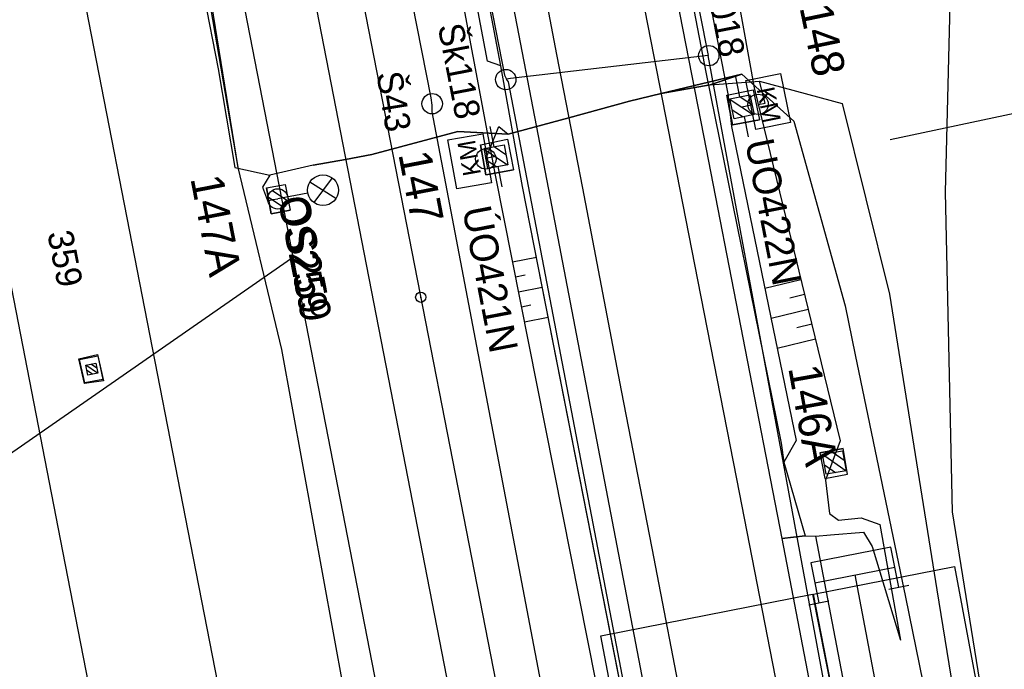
# Model space of a CAD drawing. Extents: x -545967 to -545044, y -1122650 to -1118491.
# Drawn here: x -545744.88 to -545696.59, y -1119225.35 to -1119193.49 of the extents above; entities that cross this region are included whole.
import ezdxf

# ---------------------------------------------------------------- set-up
doc = ezdxf.new("R2010")
doc.units = 0
for name, color, linetype in [('osvětlené plochy-hodnota-obrys', 7, 'Continuous'), ('Vrstva 1', 7, 'Continuous'), ('Vrstva 1 - Koleje', 7, 'Continuous'), ('Vrstva 11', 7, 'Continuous'), ('Vrstva 11 - Trakce', 7, 'Continuous'), ('Vrstva 12', 7, 'Continuous'), ('Vrstva 12 - Trakce zaklady', 7, 'Continuous'), ('Vrstva 15_zarazedla', 7, 'Continuous'), ('Vrstva 19 - Staniceni', 7, 'Continuous'), ('Vrstva 25', 7, 'Continuous'), ('Vrstva 25 - silnoproud prvky', 7, 'Continuous'), ('Vrstva 26', 7, 'Continuous'), ('Vrstva 26 - silnoproud', 7, 'Continuous'), ('Vrstva 28 - zabzar', 7, 'Continuous'), ('Vrstva 31', 7, 'Continuous'), ('Vrstva 32', 7, 'Continuous'), ('Vrstva 4 - Teren - stezky - prechody - plochy', 7, 'Continuous'), ('Vrstva 43', 7, 'Continuous'), ('Vrstva 44', 7, 'Continuous'), ('Vrstva 48', 7, 'Continuous'), ('Vrstva 49', 7, 'Continuous'), ('Vrstva 50', 7, 'Continuous'), ('Vrstva 51', 7, 'Continuous'), ('Vrstva 63', 7, 'Continuous')]:
    doc.layers.add(name, color=color, linetype=linetype)

msp = doc.modelspace()

# ---------------------------------------------------------------- linework, layer by layer
at = {"layer": 'osvětlené plochy-hodnota-obrys'}
for points in [[(-545700.341, -1119250.428), (-545705.955, -1119221.665), (-545699.039, -1119220.315), (-545660.607, -1119425.918), (-545653.752, -1119372.856), (-545653.095, -1119348.321), (-545657.119, -1119319.988), (-545685.945, -1119192.198), (-545694.33, -1119168.5)], [(-545664.282, -1119515.639), (-545680.447, -1119467.233), (-545736.202, -1119180.74), (-545730.573, -1119179.645)], [(-545730.573, -1119179.645), (-545675.345, -1119462.605), (-545660.82, -1119505.941)], [(-545716.386, -1119223.717), (-545705.994, -1119221.66), (-545669.439, -1119408.759), (-545659.4, -1119462.635), (-545647.69, -1119521.347), (-545640.519, -1119558.729), (-545633.585, -1119589.698), (-545629.517, -1119613.814), (-545623.042, -1119645.057), (-545619.034, -1119667.556), (-545607.519, -1119727.517)], [(-545610.895, -1119760.665), (-545622.836, -1119699.488), (-545637.26, -1119626.872), (-545653.542, -1119543.449), (-545716.386, -1119223.717)]]:
    msp.add_lwpolyline(points, dxfattribs=at)
at = {"layer": 'Vrstva 1'}
for points in [[(-545771.025, -1119042.195), (-545765.518, -1119070.46), (-545759.655, -1119100.537), (-545754.322, -1119127.883), (-545749.142, -1119154.443), (-545741.38, -1119194.232), (-545736.638, -1119218.552), (-545732.259, -1119241.007)], [(-545771.689, -1119071.297), (-545765.82, -1119101.405), (-545760.255, -1119129.935), (-545755.249, -1119155.634), (-545747.474, -1119195.477), (-545742.774, -1119219.556), (-545738.366, -1119242.197)], [(-545732.996, -1119179.254), (-545727.764, -1119206.17), (-545723.954, -1119225.738), (-545721.389, -1119238.891)]]:
    msp.add_lwpolyline(points, dxfattribs=at)
at = {"layer": 'Vrstva 1 - Koleje'}
for points in [[(-545733.999, -1119091.546), (-545732.95, -1119096.936), (-545731.205, -1119105.879), (-545729.373, -1119115.292), (-545728.267, -1119120.965), (-545726.468, -1119130.178), (-545724.605, -1119139.732), (-545722.574, -1119150.154), (-545720.702, -1119159.751), (-545718.638, -1119170.336), (-545716.601, -1119180.775), (-545714.642, -1119190.838), (-545712.795, -1119200.311), (-545711.639, -1119206.25), (-545709.729, -1119216.005), (-545707.216, -1119228.928), (-545705.339, -1119238.544), (-545703.888, -1119245.98)], [(-545738.202, -1119092.228), (-545736.387, -1119101.709), (-545734.567, -1119111.273), (-545732.861, -1119120.206), (-545731.063, -1119129.63), (-545729.36, -1119138.55), (-545727.68, -1119147.349), (-545726.123, -1119155.516), (-545724.233, -1119165.426), (-545722.398, -1119175.037), (-545720.387, -1119185.566), (-545718.546, -1119195.193), (-545717.286, -1119201.759), (-545715.378, -1119211.671), (-545713.882, -1119219.417), (-545712.258, -1119227.812), (-545710.337, -1119237.731), (-545708.555, -1119246.894)], [(-545703.92, -1119220.722), (-545702.554, -1119227.966), (-545700.678, -1119237.615), (-545699.221, -1119245.067)]]:
    msp.add_lwpolyline(points, dxfattribs=at)
at = {"layer": 'Vrstva 11'}
for p, q in [((-545741.057, -1119210.831), (-545741.642, -1119210.439)), ((-545741.106, -1119210.572), (-545741.384, -1119210.386)), ((-545741.317, -1119210.882), (-545741.591, -1119210.699))]:
    msp.add_line(p, q, dxfattribs=at)
for points in [[(-545693.484, -1119243.944), (-545696.51, -1119233.839), (-545699.129, -1119217.635), (-545699.471, -1119201.94)], [(-545741.546, -1119210.928), (-545741.643, -1119210.437), (-545741.152, -1119210.34), (-545741.055, -1119210.831), (-545741.546, -1119210.928)]]:
    msp.add_lwpolyline(points, dxfattribs=at)
msp.add_lwpolyline([(-545741.546, -1119210.928), (-545741.643, -1119210.437), (-545741.152, -1119210.34), (-545741.055, -1119210.831)], close=True, dxfattribs=at)
at = {"layer": 'Vrstva 11 - Trakce'}
for p, q in [((-545709.556, -1119197.274), (-545709.76, -1119196.291)), ((-545710.041, -1119197.395), (-545708.886, -1119198.151)), ((-545709.55, -1119197.268), (-545708.966, -1119197.651)), ((-545709.932, -1119197.914), (-545709.405, -1119198.259)), ((-545709.355, -1119198.239), (-545709.148, -1119199.227)), ((-545721.618, -1119199.719), (-545721.807, -1119198.733)), ((-545722.104, -1119199.833), (-545720.961, -1119200.607)), ((-545721.612, -1119199.714), (-545721.033, -1119200.106)), ((-545722.004, -1119200.354), (-545721.482, -1119200.707)), ((-545721.431, -1119200.687), (-545721.239, -1119201.679)), ((-545732.703, -1119202.17), (-545731.935, -1119202.687)), ((-545732.488, -1119201.863), (-545731.73, -1119202.373)), ((-545705.508, -1119214.803), (-545704.352, -1119215.609)), ((-545704.986, -1119214.71), (-545704.445, -1119215.088)), ((-545705.418, -1119215.322), (-545704.87, -1119215.705))]:
    msp.add_line(p, q, dxfattribs=at)
for points in [[(-545709.067, -1119197.167), (-545708.862, -1119198.146), (-545709.841, -1119198.351), (-545710.046, -1119197.372)], [(-545721.127, -1119199.621), (-545720.938, -1119200.602), (-545721.919, -1119200.791), (-545722.108, -1119199.81)], [(-545704.527, -1119214.628), (-545704.351, -1119215.612), (-545705.335, -1119215.788), (-545705.511, -1119214.804)]]:
    msp.add_lwpolyline(points, close=True, dxfattribs=at)
msp.add_circle((-545732.219, -1119202.28), 0.5, dxfattribs=at)
at = {"layer": 'Vrstva 12'}
msp.add_line((-545741.061, -1119209.905), (-545740.764, -1119211.198), dxfattribs=at)
for points in [[(-545741.974, -1119210.12), (-545741.061, -1119209.905), (-545741.043, -1119209.979)], [(-545741.703, -1119211.337), (-545741.974, -1119210.12), (-545741.945, -1119210.159)], [(-545740.806, -1119211.129), (-545740.764, -1119211.198), (-545741.703, -1119211.337), (-545741.686, -1119211.306)]]:
    msp.add_lwpolyline(points, dxfattribs=at)
msp.add_lwpolyline([(-545740.806, -1119211.129), (-545741.686, -1119211.306), (-545741.945, -1119210.159), (-545741.043, -1119209.979)], close=True, dxfattribs=at)
at = {"layer": 'Vrstva 12 - Trakce zaklady'}
for p, q in [((-545710.205, -1119197.185), (-545708.905, -1119196.923)), ((-545709.93, -1119198.644), (-545708.598, -1119198.395)), ((-545722.288, -1119199.621), (-545720.949, -1119199.355)), ((-545722.017, -1119201.095), (-545720.662, -1119200.846)), ((-545732.782, -1119201.73), (-545731.858, -1119201.572)), ((-545732.54, -1119203.006), (-545731.612, -1119202.833)), ((-545705.633, -1119214.741), (-545704.502, -1119214.523)), ((-545705.386, -1119216.001), (-545704.278, -1119215.779))]:
    msp.add_line(p, q, dxfattribs=at)
for points in [[(-545709.93, -1119198.644), (-545710.205, -1119197.185), (-545708.905, -1119196.923), (-545708.598, -1119198.395), (-545709.93, -1119198.644)], [(-545710.205, -1119197.185), (-545710.205, -1119197.185), (-545709.93, -1119198.644), (-545709.93, -1119198.644)], [(-545722.017, -1119201.095), (-545722.288, -1119199.621), (-545720.949, -1119199.355), (-545720.662, -1119200.846), (-545722.017, -1119201.095)], [(-545720.949, -1119199.355), (-545720.949, -1119199.355), (-545720.662, -1119200.846), (-545720.662, -1119200.846)], [(-545722.288, -1119199.621), (-545722.288, -1119199.621), (-545722.017, -1119201.095), (-545722.017, -1119201.095)], [(-545731.858, -1119201.572), (-545731.612, -1119202.833), (-545732.54, -1119203.006), (-545732.782, -1119201.73), (-545731.858, -1119201.572)], [(-545732.782, -1119201.73), (-545732.782, -1119201.73), (-545732.54, -1119203.006), (-545732.54, -1119203.006)], [(-545731.858, -1119201.572), (-545731.858, -1119201.572), (-545731.612, -1119202.833), (-545731.612, -1119202.833)], [(-545705.633, -1119214.741), (-545705.386, -1119216.001), (-545704.278, -1119215.779), (-545704.502, -1119214.523), (-545705.633, -1119214.741)], [(-545705.633, -1119214.741), (-545705.633, -1119214.741), (-545705.386, -1119216.001), (-545705.386, -1119216.001)]]:
    msp.add_lwpolyline(points, dxfattribs=at)
at = {"layer": 'Vrstva 15_zarazedla'}
for p, q in [((-545705.882, -1119221.108), (-545701.958, -1119220.336)), ((-545702.255, -1119221.414), (-545701.274, -1119221.221)), ((-545706.18, -1119222.185), (-545705.199, -1119221.992))]:
    msp.add_line(p, q, dxfattribs=at)
msp.add_lwpolyline([(-545701.765, -1119221.318), (-545702.15, -1119219.355), (-545706.075, -1119220.126), (-545705.69, -1119222.089)], dxfattribs=at)
at = {"layer": 'Vrstva 19 - Staniceni'}
for p, q in [((-545709.454, -1119197.759), (-545709.027, -1119197.672)), ((-545721.523, -1119200.206), (-545721.952, -1119200.283))]:
    msp.add_line(p, q, dxfattribs=at)
for points in [[(-545709.269, -1119196.477), (-545707.566, -1119196.132), (-545707.08, -1119198.525), (-545708.784, -1119198.87)], [(-545721.737, -1119201.483), (-545723.447, -1119201.791), (-545723.879, -1119199.387), (-545722.168, -1119199.08)]]:
    msp.add_lwpolyline(points, close=True, dxfattribs=at)
at = {"layer": 'Vrstva 25'}
for p, q in [((-545729.548, -1119201.252), (-545730.46, -1119202.451)), ((-545729.369, -1119202.251), (-545730.652, -1119201.46)), ((-545730.747, -1119201.992), (-545732.219, -1119202.28))]:
    msp.add_line(p, q, dxfattribs=at)
msp.add_circle((-545730.006, -1119201.85), 0.754, dxfattribs=at)
at = {"layer": 'Vrstva 25 - silnoproud prvky'}
for p, q in [((-545708.68, -1119197.591), (-545708.66, -1119197.689)), ((-545722.029, -1119200.271), (-545722.011, -1119200.369)), ((-545729.548, -1119201.252), (-545730.46, -1119202.451)), ((-545729.369, -1119202.251), (-545730.652, -1119201.46)), ((-545730.747, -1119201.992), (-545732.219, -1119202.28))]:
    msp.add_line(p, q, dxfattribs=at)
for centre, radius in [((-545708.67, -1119197.64), 0.5), ((-545722.02, -1119200.32), 0.5), ((-545730.006, -1119201.85), 0.754)]:
    msp.add_circle(centre, radius, dxfattribs=at)
at = {"layer": 'Vrstva 26'}
for points in [[(-545709.47, -1119196.16), (-545713.419, -1119197.11), (-545714.968, -1119197.483), (-545717.951, -1119198.296), (-545720.917, -1119199.104), (-545723.4, -1119198.98), (-545727.61, -1119200.1), (-545728.9, -1119200.338), (-545730.48, -1119200.63)], [(-545723.4, -1119198.98), (-545720.917, -1119199.104), (-545717.951, -1119198.296), (-545714.968, -1119197.483), (-545713.419, -1119197.11), (-545709.47, -1119196.16), (-545706.908, -1119198.458), (-545704.395, -1119207.525), (-545703.903, -1119209.931), (-545701.434, -1119221.82), (-545699.39, -1119231.84), (-545698.841, -1119235.301), (-545696.65, -1119244.564)], [(-545723.4, -1119198.98), (-545727.61, -1119200.1), (-545728.9, -1119200.338), (-545730.48, -1119200.63), (-545732.62, -1119201.11), (-545732.98, -1119201.71), (-545732.72, -1119202.36), (-545732.718, -1119202.365), (-545732.46, -1119202.3), (-545732.219, -1119202.28)]]:
    msp.add_lwpolyline(points, dxfattribs=at)
at = {"layer": 'Vrstva 26 - silnoproud'}
for points in [[(-545748.72, -1119088.787), (-545745.498, -1119105.777), (-545744.592, -1119110.019), (-545739.382, -1119138.558), (-545737.893, -1119145.12), (-545736.243, -1119151.98), (-545735.253, -1119157.79), (-545734.753, -1119161.66), (-545734.703, -1119163.85), (-545735.243, -1119167.68), (-545737.053, -1119172.51), (-545737.303, -1119173.49), (-545737.953, -1119181.49), (-545735.153, -1119195.905), (-545734.323, -1119200.74), (-545732.62, -1119201.11)], [(-545730.48, -1119200.63), (-545728.9, -1119200.338), (-545727.61, -1119200.1), (-545723.4, -1119198.98), (-545720.917, -1119199.104), (-545717.951, -1119198.296), (-545714.968, -1119197.483), (-545713.419, -1119197.11), (-545711.01, -1119196.68), (-545709.47, -1119196.16)], [(-545709.47, -1119196.16), (-545711.01, -1119196.68), (-545713.419, -1119197.11), (-545714.968, -1119197.483), (-545717.951, -1119198.296), (-545720.917, -1119199.104), (-545723.4, -1119198.98), (-545727.61, -1119200.1), (-545728.9, -1119200.338), (-545730.48, -1119200.63)], [(-545723.4, -1119198.98), (-545720.917, -1119199.104), (-545717.951, -1119198.296), (-545714.968, -1119197.483), (-545713.419, -1119197.11), (-545711.01, -1119196.68), (-545709.47, -1119196.16), (-545706.908, -1119198.458), (-545704.395, -1119207.525), (-545703.903, -1119209.931), (-545701.434, -1119221.82), (-545699.39, -1119231.84), (-545698.841, -1119235.301), (-545696.65, -1119244.564)], [(-545723.4, -1119198.98), (-545720.917, -1119199.104), (-545717.951, -1119198.296), (-545714.968, -1119197.483), (-545713.419, -1119197.11), (-545711.01, -1119196.68), (-545709.47, -1119196.16), (-545706.908, -1119198.458), (-545704.395, -1119207.525), (-545703.903, -1119209.931), (-545701.434, -1119221.82), (-545699.39, -1119231.84), (-545698.841, -1119235.301), (-545696.65, -1119244.564)], [(-545720.917, -1119199.104), (-545717.951, -1119198.296), (-545714.968, -1119197.483), (-545713.419, -1119197.11), (-545711.01, -1119196.68), (-545709.47, -1119196.16)], [(-545722.02, -1119200.32), (-545721.39, -1119198.73), (-545720.917, -1119199.104), (-545717.951, -1119198.296), (-545714.968, -1119197.483), (-545713.419, -1119197.11), (-545711.01, -1119196.68), (-545708.6, -1119196.51)], [(-545708.67, -1119197.64), (-545708.32, -1119197.58), (-545708.6, -1119196.51), (-545704.54, -1119197.6), (-545702.23, -1119206.95), (-545699.9, -1119221.45), (-545698.219, -1119231.843), (-545695.098, -1119244.26)], [(-545723.4, -1119198.98), (-545727.61, -1119200.1), (-545728.9, -1119200.338), (-545730.48, -1119200.63), (-545732.62, -1119201.11), (-545732.98, -1119201.71), (-545732.72, -1119202.36), (-545732.718, -1119202.365), (-545732.46, -1119202.3), (-545732.219, -1119202.28)], [(-545723.4, -1119198.98), (-545727.61, -1119200.1), (-545728.9, -1119200.338), (-545730.48, -1119200.63), (-545732.62, -1119201.11)]]:
    msp.add_lwpolyline(points, dxfattribs=at)
at = {"layer": 'Vrstva 28 - zabzar'}
msp.add_lwpolyline([(-545724.371, -1119249.989), (-545724.69, -1119248.61), (-545727.23, -1119235.34), (-545728.99, -1119226.34), (-545732.03, -1119209.67), (-545734.16, -1119200.74), (-545735.82, -1119191.07), (-545737.79, -1119181.49), (-545737.14, -1119173.49), (-545736.89, -1119172.51), (-545735.08, -1119167.68), (-545734.54, -1119163.85), (-545734.59, -1119161.66), (-545735.09, -1119157.79), (-545736.08, -1119151.98), (-545737.73, -1119145.12), (-545739.97, -1119133.32), (-545740.77, -1119128.56), (-545744.45, -1119110.05), (-545745.46, -1119105.77), (-545746.9, -1119097.66), (-545750.31, -1119079.79)], dxfattribs=at)
at = {"layer": 'Vrstva 31'}
msp.add_lwpolyline([(-545724.371, -1119249.989), (-545724.69, -1119248.61), (-545727.23, -1119235.34), (-545728.99, -1119226.34), (-545732.03, -1119209.67), (-545734.16, -1119200.74), (-545735.82, -1119191.07), (-545737.79, -1119181.49), (-545737.14, -1119173.49), (-545736.89, -1119172.51), (-545735.08, -1119167.68), (-545734.54, -1119163.85), (-545734.59, -1119161.66), (-545735.09, -1119157.79), (-545736.08, -1119151.98), (-545737.73, -1119145.12), (-545739.97, -1119133.32), (-545740.77, -1119128.56), (-545744.45, -1119110.05), (-545745.46, -1119105.77), (-545746.9, -1119097.66), (-545750.31, -1119079.79)], dxfattribs=at)
at = {"layer": 'Vrstva 32'}
msp.add_lwpolyline([(-545724.371, -1119249.989), (-545724.69, -1119248.61), (-545727.23, -1119235.34), (-545728.99, -1119226.34), (-545732.03, -1119209.67), (-545734.16, -1119200.74), (-545735.66, -1119191.53), (-545735.82, -1119191.07), (-545737.79, -1119181.49), (-545737.14, -1119173.49), (-545736.89, -1119172.51), (-545735.08, -1119167.68), (-545734.54, -1119163.85), (-545734.59, -1119161.66), (-545735.09, -1119157.79), (-545736.08, -1119151.98), (-545737.73, -1119145.12), (-545739.97, -1119133.32), (-545740.77, -1119128.56), (-545744.45, -1119110.05), (-545745.46, -1119105.77), (-545746.9, -1119097.66), (-545750.31, -1119079.79)], dxfattribs=at)
at = {"layer": 'Vrstva 4 - Teren - stezky - prechody - plochy'}
for points in [[(-545842.991, -1118523.919), (-545841.705, -1118530.396), (-545836.849, -1118554.447), (-545831.054, -1118584.604), (-545819.351, -1118645.264), (-545811.232, -1118686.911), (-545799.532, -1118746.647), (-545788.535, -1118802.768), (-545777.847, -1118857.696), (-545765.826, -1118919.341), (-545755.98, -1118970.183), (-545745.509, -1119023.121), (-545734.813, -1119078.883), (-545723.148, -1119138.675), (-545711.327, -1119199.256), (-545707.51, -1119218.932), (-545706.355, -1119218.803)], [(-545711.324, -1119247.435), (-545711.901, -1119243.963), (-545720.224, -1119201.665), (-545721.285, -1119195.757), (-545731.546, -1119141.712), (-545737.081, -1119112.42), (-545743.441, -1119079.103), (-545754.278, -1119022.005), (-545764.127, -1118971.243), (-545774.702, -1118917.119), (-545786.098, -1118858.181), (-545797.005, -1118803.413), (-545807.661, -1118749.422), (-545819.911, -1118686.431), (-545828.531, -1118641.36), (-545850.15, -1118530.525), (-545851.156, -1118525.517)], [(-545710.225, -1119247.22), (-545719.004, -1119201.386), (-545730.622, -1119141.385), (-545736.208, -1119112.206), (-545742.564, -1119078.927), (-545753.414, -1119021.814), (-545763.359, -1118970.942), (-545773.922, -1118916.709), (-545785.328, -1118858.188), (-545796.206, -1118802.914), (-545806.845, -1118748.63), (-545819.206, -1118686.191), (-545827.818, -1118641.013), (-545849.345, -1118530.249), (-545850.409, -1118525.371)], [(-545787.709, -1118802.92), (-545777.141, -1118857.583), (-545765.122, -1118918.891), (-545755.123, -1118970.549), (-545744.471, -1119024.933), (-545734.117, -1119078.34), (-545722.331, -1119138.405), (-545711.219, -1119196.145), (-545707.543, -1119214.266), (-545707.412, -1119215.197), (-545706.355, -1119218.803)], [(-545706.355, -1119218.803), (-545707.51, -1119218.932), (-545702.452, -1119245.262), (-545702.369, -1119245.683)], [(-545706.355, -1119218.803), (-545705.856, -1119218.828), (-545700.854, -1119244.947), (-545700.771, -1119245.37)]]:
    msp.add_lwpolyline(points, dxfattribs=at)
at = {"layer": 'Vrstva 43'}
for centre in [(-545711.085, -1119195.252), (-545721.043, -1119196.425), (-545724.651, -1119197.609)]:
    msp.add_circle(centre, 0.5, dxfattribs=at)
at = {"layer": 'Vrstva 44'}
for points in [[(-545744.065, -1119094.166), (-545734.822, -1119146.139), (-545734.752, -1119146.549), (-545734.659, -1119146.89), (-545724.724, -1119197.313), (-545724.661, -1119197.687), (-545724.663, -1119198.006), (-545716.416, -1119241.322), (-545716.376, -1119241.688), (-545716.362, -1119242.059), (-545715.179, -1119248.19)], [(-545730.081, -1119098.833), (-545720.599, -1119147.438), (-545711.114, -1119195.247), (-545720.817, -1119196.365), (-545721.01, -1119196.412)], [(-545739.309, -1119100.743), (-545730.259, -1119149.369), (-545721.097, -1119196.213), (-545721.01, -1119196.412)], [(-545701.67, -1119245.546), (-545703.847, -1119234.609), (-545711.114, -1119195.247)], [(-545711.13, -1119247.397), (-545713.208, -1119236.715), (-545720.909, -1119196.537), (-545721.01, -1119196.412)]]:
    msp.add_lwpolyline(points, dxfattribs=at)
at = {"layer": 'Vrstva 48'}
for p, q in [((-545720.708, -1119205.362), (-545719.542, -1119205.131)), ((-545720.562, -1119206.098), (-545720.096, -1119206.005)), ((-545720.416, -1119206.833), (-545719.252, -1119206.602)), ((-545706.566, -1119206.244), (-545708.33, -1119206.674)), ((-545706.388, -1119206.973), (-545707.105, -1119207.147)), ((-545720.27, -1119207.569), (-545719.805, -1119207.477)), ((-545720.124, -1119208.305), (-545718.963, -1119208.074)), ((-545706.211, -1119207.701), (-545708.027, -1119208.144)), ((-545706.034, -1119208.43), (-545706.77, -1119208.61)), ((-545705.856, -1119209.159), (-545707.724, -1119209.614))]:
    msp.add_line(p, q, dxfattribs=at)
at = {"layer": 'Vrstva 49'}
for points in [[(-545839.308, -1118523.198), (-545838.102, -1118529.579), (-545837.4, -1118533.485), (-545832.706, -1118555.695), (-545825.144, -1118594.377), (-545814.251, -1118651.352), (-545808.026, -1118685.152), (-545795.162, -1118750.192), (-545783.943, -1118809.71), (-545774.848, -1118856.951), (-545763.418, -1118915.038), (-545752.928, -1118968.655), (-545741.707, -1119025.946), (-545730.219, -1119081.986), (-545719.001, -1119141.326), (-545708.857, -1119196.833), (-545704.642, -1119214.146)], [(-545785.57, -1118809.023), (-545776.461, -1118857.744), (-545776.223, -1118859.028), (-545764.986, -1118916.441), (-545764.658, -1118917.886), (-545754.446, -1118970.66), (-545754.175, -1118971.989), (-545744.319, -1119022.631), (-545744.059, -1119023.95), (-545733.435, -1119078.425), (-545721.625, -1119138.52), (-545721.391, -1119139.742), (-545710.151, -1119197.125), (-545709.969, -1119198.727), (-545706.792, -1119214.135), (-545707.412, -1119215.197), (-545706.355, -1119218.803), (-545705.856, -1119218.828), (-545705.109, -1119218.756), (-545703.505, -1119218.63), (-545703.071, -1119219.321), (-545701.68, -1119223.926)], [(-545712.345, -1119247.635), (-545712.918, -1119244.626), (-545721.552, -1119201.108), (-545732.642, -1119141.942), (-545733.194, -1119140.665), (-545738.437, -1119113.17), (-545744.258, -1119082.787), (-545744.781, -1119080.348), (-545754.155, -1119031.651), (-545755.213, -1119026.18), (-545765.268, -1118974.147), (-545765.5, -1118972.759), (-545775.821, -1118920.177), (-545776.085, -1118918.771), (-545787.25, -1118861.285), (-545787.565, -1118859.78), (-545796.822, -1118811.001)], [(-545711.324, -1119247.435), (-545711.901, -1119243.963), (-545720.224, -1119201.665), (-545721.285, -1119195.757), (-545721.943, -1119195.521), (-545732.082, -1119141.82), (-545732.265, -1119140.515), (-545737.739, -1119112.717), (-545743.315, -1119083.132), (-545744.039, -1119079.561), (-545753.263, -1119031.334), (-545754.002, -1119028.935), (-545754.148, -1119025.929), (-545754.487, -1119024.319), (-545754.825, -1119024.298), (-545764.544, -1118973.992), (-545764.787, -1118972.577), (-545775.108, -1118920.03), (-545775.396, -1118918.541), (-545786.585, -1118861.093), (-545786.924, -1118859.548), (-545796.323, -1118810.897)], [(-545704.642, -1119214.146), (-545705.357, -1119216.073), (-545705.159, -1119217.704), (-545704.722, -1119218.044), (-545703.605, -1119217.918), (-545702.704, -1119218.243), (-545701.68, -1119223.926)]]:
    msp.add_lwpolyline(points, dxfattribs=at)
at = {"layer": 'Vrstva 50'}
msp.add_line((-545725.238, -1119207.103), (-545725.188, -1119207.103), dxfattribs=at)
msp.add_circle((-545725.213, -1119207.103), 0.25, dxfattribs=at)
at = {"layer": 'Vrstva 51'}
msp.add_lwpolyline([(-545699.471, -1119201.94), (-545698.549, -1119164.446), (-545694.235, -1119158.917), (-545692.241, -1119158.084), (-545688.341, -1119153.091), (-545685.062, -1119149.37), (-545681.978, -1119143.375)], dxfattribs=at)
at = {"layer": 'Vrstva 63'}
for p, q in [((-545607.451, -1119179.265), (-545702.192, -1119199.374)), ((-545731.55, -1119205.203), (-545759.831, -1119224.85))]:
    msp.add_line(p, q, dxfattribs=at)

# ---------------------------------------------------------------- texts
at = {"layer": 'Vrstva 11'}
msp.add_text('359', height=1.25, rotation=281.1614, dxfattribs=at).set_placement((-545743.534, -1119203.956))
at = {"layer": 'Vrstva 11 - Trakce'}
for s, rotation, p in [('148', 281.7807, (-545706.642, -1119192.88)), ('147', 280.8955, (-545726.317, -1119200.079)), ('147A', 281.0388, (-545736.516, -1119201.265)), ('146A', 280.112, (-545707.195, -1119210.56))]:
    msp.add_text(s, height=1.6, rotation=rotation, dxfattribs=at).set_placement(p)
at = {"layer": 'Vrstva 19 - Staniceni'}
for rotation, p in [(281.4673, (-545708.743, -1119196.888)), (100.1811, (-545722.253, -1119201.06))]:
    msp.add_text('KM', height=0.8728, rotation=rotation, dxfattribs=at).set_placement(p)
at = {"layer": 'Vrstva 25'}
msp.add_text('OS259', height=1.5, rotation=281.0737, dxfattribs=at).set_placement((-545732.219, -1119202.28))
at = {"layer": 'Vrstva 25 - silnoproud prvky'}
for s, rotation, p in [('UO422N', 281.0176, (-545709.308, -1119199.475)), ('OS259', 281.0737, (-545732.219, -1119202.28)), ('ÚO421N', 280.8942, (-545723.176, -1119202.768))]:
    msp.add_text(s, height=1.4, rotation=rotation, dxfattribs=at).set_placement(p)
at = {"layer": 'Vrstva 43'}
for s, rotation, p in [('Šp018', 280.9998, (-545711.442, -1119190.66)), ('Šk118', 280.9998, (-545724.384, -1119193.796)), ('Š43', 279.317, (-545727.386, -1119196.127))]:
    msp.add_text(s, height=1.25, rotation=rotation, dxfattribs=at).set_placement(p)

doc.saveas('drawing.dxf')
